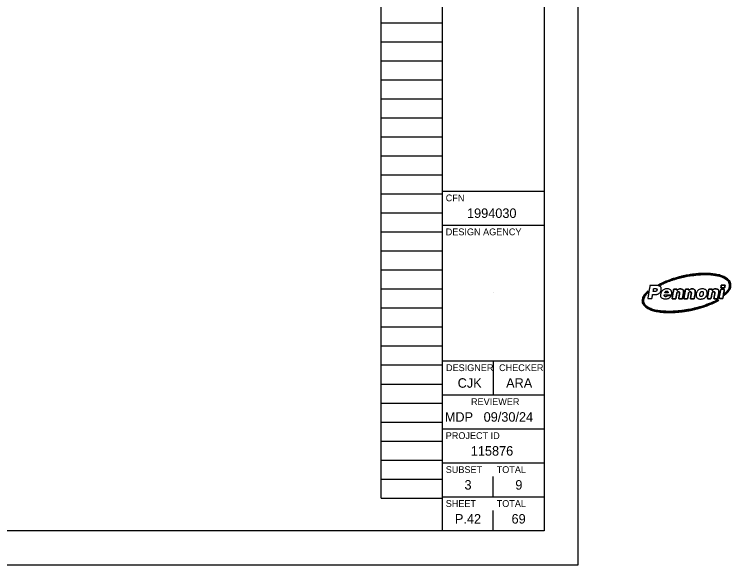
# Model space of a CAD drawing. Extents: x 0 to 36.2, y 0 to 22.
# Drawn here: x 25.7 to 36.25, y 0 to 8.1 of the extents above; entities that cross this region are included whole.
import ezdxf

# ---------------------------------------------------------------- set-up
doc = ezdxf.new("R2010")
doc.units = 0
for name, color, linetype in [('SC_Scratch1', 7, 'Continuous'), ('SH_Border', 7, 'Continuous'), ('SH_Cut_Line', 7, 'Continuous'), ('SH_Data', 7, 'Continuous')]:
    doc.layers.add(name, color=color, linetype=linetype)

msp = doc.modelspace()

# ---------------------------------------------------------------- linework, layer by layer
at = {"layer": 'SC_Scratch1'}
for p, q in [((31.1, 0.98), (31.1, 21.14)), ((32, 0.98), (32, 21.14)), ((31.1, 7.98), (32, 7.98)), ((31.1, 7.7), (32, 7.7)), ((31.1, 7.42), (32, 7.42)), ((31.1, 7.14), (32, 7.14)), ((31.1, 6.86), (32, 6.86)), ((31.1, 6.58), (32, 6.58)), ((31.1, 6.3), (32, 6.3)), ((31.1, 6.02), (32, 6.02)), ((31.1, 5.74), (32, 5.74)), ((31.1, 5.46), (32, 5.46)), ((31.1, 5.18), (32, 5.18)), ((31.1, 4.9), (32, 4.9)), ((31.1, 4.62), (32, 4.62)), ((31.1, 4.34), (32, 4.34)), ((31.1, 4.06), (32, 4.06)), ((31.1, 3.78), (32, 3.78)), ((31.1, 3.5), (32, 3.5)), ((31.1, 3.22), (32, 3.22)), ((31.1, 2.94), (32, 2.94)), ((31.1, 2.66), (32, 2.66)), ((31.1, 2.38), (32, 2.38)), ((31.1, 2.1), (32, 2.1)), ((31.1, 1.82), (32, 1.82)), ((31.1, 1.54), (32, 1.54)), ((31.1, 1.26), (32, 1.26)), ((31.1, 0.98), (32, 0.98))]:
    msp.add_line(p, q, dxfattribs=at)
at = {"layer": 'SH_Border'}
for p, q in [((32, 0.5), (32, 21.5)), ((32, 5.5), (33.5, 5.5)), ((32, 5), (33.5, 5)), ((35.325, 4.003), (35.275, 4.003)), ((32, 3), (33.5, 3)), ((32.75, 3), (32.75, 2.5)), ((32, 2.5), (33.5, 2.5)), ((32, 2), (33.5, 2)), ((32, 1.5), (33.5, 1.5)), ((32, 1), (33.5, 1))]:
    msp.add_line(p, q, dxfattribs=at)
msp.add_lwpolyline([(1.5, 21.5), (33.5, 21.5), (33.5, 0.5), (1.5, 0.5)], close=True, dxfattribs=at)
for points, degree in [([(35.184, 4.121), (35.191, 4.119), (35.197, 4.116), (35.203, 4.115), (35.205, 4.114), (35.208, 4.114), (35.21, 4.115), (35.239, 4.129), (35.267, 4.143), (35.296, 4.155), (35.337, 4.173), (35.38, 4.188), (35.423, 4.201), (35.465, 4.214), (35.507, 4.225), (35.55, 4.234), (35.59, 4.243), (35.63, 4.251), (35.67, 4.256), (35.702, 4.26), (35.734, 4.264), (35.766, 4.267), (35.791, 4.269), (35.817, 4.27), (35.842, 4.271), (35.897, 4.272), (35.952, 4.27), (36.007, 4.262), (36.036, 4.258), (36.066, 4.252), (36.094, 4.242), (36.13, 4.231), (36.163, 4.217), (36.191, 4.191), (36.206, 4.178), (36.218, 4.161), (36.223, 4.141), (36.228, 4.124), (36.23, 4.107), (36.227, 4.089), (36.223, 4.069), (36.213, 4.052), (36.201, 4.036), (36.189, 4.021), (36.175, 4.008), (36.16, 3.995), (36.158, 3.994), (36.157, 3.992), (36.156, 3.99), (36.155, 3.985), (36.154, 3.979), (36.153, 3.973), (36.153, 3.971), (36.152, 3.969), (36.152, 3.965), (36.176, 3.985), (36.199, 4.005), (36.217, 4.029), (36.226, 4.04), (36.234, 4.053), (36.239, 4.066), (36.246, 4.085), (36.246, 4.104), (36.244, 4.123), (36.24, 4.158), (36.224, 4.185), (36.198, 4.208), (36.174, 4.228), (36.147, 4.241), (36.117, 4.252), (36.08, 4.266), (36.042, 4.274), (36.003, 4.279), (35.968, 4.284), (35.933, 4.287), (35.897, 4.288), (35.841, 4.289), (35.785, 4.287), (35.729, 4.281), (35.698, 4.277), (35.667, 4.273), (35.636, 4.268), (35.591, 4.261), (35.546, 4.252), (35.502, 4.24), (35.441, 4.225), (35.382, 4.207), (35.323, 4.184), (35.283, 4.169), (35.243, 4.151), (35.204, 4.131), (35.197, 4.128), (35.191, 4.125), (35.184, 4.121)], 3), ([(35.184, 4.121), (35.191, 4.125), (35.197, 4.128), (35.204, 4.131), (35.243, 4.151), (35.283, 4.169), (35.323, 4.184), (35.382, 4.207), (35.441, 4.225), (35.502, 4.24), (35.546, 4.252), (35.591, 4.261), (35.636, 4.268), (35.667, 4.273), (35.698, 4.277), (35.729, 4.281), (35.785, 4.287), (35.841, 4.289), (35.897, 4.288), (35.933, 4.287), (35.968, 4.284), (36.003, 4.279), (36.042, 4.274), (36.08, 4.266), (36.117, 4.252), (36.147, 4.241), (36.174, 4.228), (36.198, 4.208), (36.224, 4.185), (36.24, 4.158), (36.244, 4.123), (36.246, 4.104), (36.246, 4.085), (36.239, 4.066), (36.234, 4.053), (36.226, 4.04), (36.217, 4.029), (36.199, 4.005), (36.176, 3.985), (36.152, 3.965), (36.152, 3.969), (36.153, 3.971), (36.153, 3.973), (36.154, 3.979), (36.155, 3.985), (36.156, 3.99), (36.157, 3.992), (36.158, 3.994), (36.16, 3.995), (36.175, 4.008), (36.189, 4.021), (36.201, 4.036), (36.213, 4.052), (36.223, 4.069), (36.227, 4.089), (36.23, 4.107), (36.228, 4.124), (36.223, 4.141), (36.218, 4.161), (36.206, 4.178), (36.191, 4.191), (36.163, 4.217), (36.13, 4.231), (36.094, 4.242), (36.066, 4.252), (36.036, 4.258), (36.007, 4.262), (35.952, 4.27), (35.897, 4.272), (35.842, 4.271), (35.817, 4.27), (35.791, 4.269), (35.766, 4.267), (35.734, 4.264), (35.702, 4.26), (35.67, 4.256), (35.63, 4.251), (35.59, 4.243), (35.55, 4.234), (35.507, 4.225), (35.465, 4.214), (35.423, 4.201), (35.38, 4.188), (35.337, 4.173), (35.296, 4.155), (35.267, 4.143), (35.239, 4.129), (35.21, 4.115), (35.208, 4.114), (35.205, 4.114), (35.203, 4.115), (35.197, 4.116), (35.191, 4.119), (35.184, 4.121)], 3), ([(36.164, 4.115), (36.162, 4.103), (36.16, 4.091), (36.157, 4.078), (36.157, 4.077), (36.156, 4.076), (36.155, 4.076), (36.137, 4.076), (36.12, 4.076), (36.102, 4.076), (36.103, 4.086), (36.105, 4.095), (36.107, 4.104), (36.107, 4.106), (36.108, 4.109), (36.108, 4.111), (36.108, 4.115), (36.109, 4.116), (36.113, 4.115), (36.129, 4.115), (36.144, 4.115), (36.16, 4.115), (36.161, 4.115), (36.162, 4.115), (36.164, 4.115)], 3), ([(36.164, 4.115), (36.162, 4.115), (36.161, 4.115), (36.16, 4.115), (36.144, 4.115), (36.129, 4.115), (36.113, 4.115), (36.109, 4.116), (36.108, 4.115), (36.108, 4.111), (36.108, 4.109), (36.107, 4.106), (36.107, 4.104), (36.105, 4.095), (36.103, 4.086), (36.102, 4.076), (36.12, 4.076), (36.137, 4.076), (36.155, 4.076), (36.156, 4.076), (36.157, 4.077), (36.157, 4.078), (36.16, 4.091), (36.162, 4.103), (36.164, 4.115)], 3), ([(36.072, 3.892), (36.072, 3.892), (36.072, 3.893), (36.072, 3.893), (36.062, 3.893), (36.052, 3.893), (36.042, 3.893), (36.04, 3.893), (36.037, 3.892), (36.035, 3.891), (35.997, 3.872), (35.959, 3.855), (35.92, 3.84), (35.862, 3.817), (35.803, 3.798), (35.743, 3.783), (35.7, 3.771), (35.657, 3.762), (35.613, 3.754), (35.588, 3.75), (35.563, 3.746), (35.538, 3.742), (35.513, 3.739), (35.487, 3.736), (35.461, 3.734), (35.437, 3.732), (35.413, 3.73), (35.389, 3.73), (35.361, 3.729), (35.333, 3.728), (35.305, 3.729), (35.274, 3.731), (35.243, 3.733), (35.212, 3.736), (35.174, 3.74), (35.136, 3.748), (35.1, 3.759), (35.068, 3.769), (35.038, 3.782), (35.011, 3.802), (34.995, 3.814), (34.98, 3.829), (34.971, 3.848), (34.959, 3.874), (34.96, 3.9), (34.971, 3.927), (34.98, 3.95), (34.994, 3.97), (35.011, 3.988), (35.016, 3.994), (35.022, 4), (35.022, 4.009), (35.022, 4.014), (35.024, 4.02), (35.025, 4.026), (35.024, 4.025), (35.023, 4.025), (35.022, 4.024), (35.013, 4.014), (35.003, 4.005), (34.994, 3.994), (34.974, 3.972), (34.959, 3.948), (34.95, 3.919), (34.946, 3.902), (34.944, 3.885), (34.947, 3.868), (34.952, 3.841), (34.967, 3.819), (34.986, 3.801), (35.009, 3.78), (35.036, 3.766), (35.064, 3.754), (35.111, 3.735), (35.161, 3.725), (35.211, 3.719), (35.241, 3.716), (35.273, 3.714), (35.304, 3.712), (35.346, 3.711), (35.388, 3.711), (35.43, 3.715), (35.465, 3.717), (35.499, 3.721), (35.533, 3.725), (35.564, 3.729), (35.594, 3.734), (35.625, 3.739), (35.679, 3.749), (35.733, 3.761), (35.786, 3.776), (35.831, 3.789), (35.876, 3.804), (35.92, 3.821), (35.963, 3.838), (36.005, 3.856), (36.046, 3.877), (36.055, 3.882), (36.063, 3.887), (36.072, 3.892)], 3), ([(36.072, 3.892), (36.063, 3.887), (36.055, 3.882), (36.046, 3.877), (36.005, 3.856), (35.963, 3.838), (35.92, 3.821), (35.876, 3.804), (35.831, 3.789), (35.786, 3.776), (35.733, 3.761), (35.679, 3.749), (35.625, 3.739), (35.594, 3.734), (35.564, 3.729), (35.533, 3.725), (35.499, 3.721), (35.465, 3.717), (35.43, 3.715), (35.388, 3.711), (35.346, 3.711), (35.304, 3.712), (35.273, 3.714), (35.241, 3.716), (35.211, 3.719), (35.161, 3.725), (35.111, 3.735), (35.064, 3.754), (35.036, 3.766), (35.009, 3.78), (34.986, 3.801), (34.967, 3.819), (34.952, 3.841), (34.947, 3.868), (34.944, 3.885), (34.946, 3.902), (34.95, 3.919), (34.959, 3.948), (34.974, 3.972), (34.994, 3.994), (35.003, 4.005), (35.013, 4.014), (35.022, 4.024), (35.023, 4.025), (35.024, 4.025), (35.025, 4.026), (35.024, 4.02), (35.022, 4.014), (35.022, 4.009), (35.022, 4), (35.016, 3.994), (35.011, 3.988), (34.994, 3.97), (34.98, 3.95), (34.971, 3.927), (34.96, 3.9), (34.959, 3.874), (34.971, 3.848), (34.98, 3.829), (34.995, 3.814), (35.011, 3.802), (35.038, 3.782), (35.068, 3.769), (35.1, 3.759), (35.136, 3.748), (35.174, 3.74), (35.212, 3.736), (35.243, 3.733), (35.274, 3.731), (35.305, 3.729), (35.333, 3.728), (35.361, 3.729), (35.389, 3.73), (35.413, 3.73), (35.437, 3.732), (35.461, 3.734), (35.487, 3.736), (35.513, 3.739), (35.538, 3.742), (35.563, 3.746), (35.588, 3.75), (35.613, 3.754), (35.657, 3.762), (35.7, 3.771), (35.743, 3.783), (35.803, 3.798), (35.862, 3.817), (35.92, 3.84), (35.959, 3.855), (35.997, 3.872), (36.035, 3.891), (36.037, 3.892), (36.04, 3.893), (36.042, 3.893), (36.052, 3.893), (36.062, 3.893), (36.072, 3.893), (36.072, 3.893), (36.072, 3.892), (36.072, 3.892)], 3), ([(35.196, 4.102), (35.183, 4.108), (35.17, 4.11), (35.156, 4.11), (35.124, 4.111), (35.092, 4.11), (35.061, 4.11), (35.059, 4.11), (35.058, 4.11), (35.057, 4.108), (35.053, 4.086), (35.05, 4.065), (35.046, 4.043), (35.04, 4.009), (35.034, 3.974), (35.028, 3.939), (35.026, 3.932), (35.025, 3.924), (35.024, 3.917)], 3), ([(35.097, 3.977), (35.105, 3.977), (35.112, 3.977), (35.119, 3.977), (35.132, 3.977), (35.145, 3.977), (35.157, 3.98), (35.174, 3.983), (35.189, 3.99), (35.201, 4.002), (35.216, 4.018), (35.222, 4.037), (35.222, 4.059), (35.223, 4.078), (35.214, 4.093), (35.196, 4.102)], 3), ([(35.105, 4.022), (35.108, 4.036), (35.11, 4.05), (35.112, 4.063), (35.113, 4.064), (35.114, 4.065), (35.115, 4.065), (35.126, 4.065), (35.138, 4.067), (35.149, 4.063), (35.159, 4.06), (35.163, 4.054), (35.161, 4.043)], 3), ([(35.161, 4.043), (35.159, 4.031), (35.15, 4.023), (35.137, 4.022), (35.127, 4.022), (35.116, 4.022), (35.105, 4.022)], 3), ([(35.377, 4.008), (35.373, 4.033), (35.36, 4.05), (35.336, 4.057), (35.323, 4.062), (35.309, 4.062), (35.296, 4.061), (35.274, 4.058), (35.255, 4.049), (35.239, 4.032), (35.225, 4.017), (35.217, 4), (35.215, 3.979), (35.212, 3.95), (35.224, 3.926), (35.253, 3.917), (35.269, 3.912), (35.286, 3.911), (35.302, 3.914), (35.32, 3.916), (35.336, 3.922), (35.35, 3.934), (35.358, 3.941), (35.364, 3.949), (35.368, 3.959)], 3), ([(35.275, 4.003), (35.276, 4.015), (35.286, 4.025), (35.298, 4.027), (35.304, 4.028), (35.31, 4.028), (35.315, 4.025), (35.323, 4.021), (35.327, 4.013), (35.325, 4.003)], 3), ([(35.383, 3.916), (35.383, 3.915), (35.384, 3.915), (35.385, 3.915), (35.402, 3.915), (35.419, 3.915), (35.436, 3.915), (35.438, 3.915), (35.438, 3.916), (35.439, 3.918), (35.44, 3.926), (35.441, 3.935), (35.443, 3.943), (35.446, 3.96), (35.449, 3.978), (35.453, 3.995), (35.455, 4.005), (35.459, 4.013), (35.469, 4.015), (35.482, 4.019), (35.496, 4.016), (35.494, 3.997), (35.492, 3.982), (35.489, 3.968), (35.487, 3.954), (35.485, 3.941), (35.482, 3.928), (35.48, 3.916), (35.481, 3.915), (35.481, 3.915), (35.482, 3.915), (35.499, 3.915), (35.516, 3.915), (35.533, 3.915), (35.535, 3.915), (35.536, 3.916), (35.536, 3.919), (35.54, 3.942), (35.545, 3.966), (35.549, 3.99), (35.551, 4.002), (35.553, 4.015), (35.551, 4.027), (35.549, 4.043), (35.54, 4.054), (35.524, 4.058), (35.503, 4.064), (35.483, 4.06), (35.466, 4.045), (35.462, 4.042), (35.458, 4.038), (35.454, 4.035), (35.456, 4.042), (35.457, 4.049), (35.458, 4.057), (35.442, 4.057), (35.425, 4.057), (35.409, 4.056), (35.408, 4.056), (35.407, 4.055), (35.407, 4.054), (35.406, 4.05), (35.405, 4.045), (35.405, 4.041), (35.399, 4.011), (35.394, 3.98), (35.389, 3.95), (35.387, 3.938), (35.385, 3.927), (35.383, 3.916)], 3), ([(35.383, 3.916), (35.385, 3.927), (35.387, 3.938), (35.389, 3.95), (35.394, 3.98), (35.399, 4.011), (35.405, 4.041), (35.405, 4.045), (35.406, 4.05), (35.407, 4.054), (35.407, 4.055), (35.408, 4.056), (35.409, 4.056), (35.425, 4.057), (35.442, 4.057), (35.458, 4.057), (35.457, 4.049), (35.456, 4.042), (35.454, 4.035), (35.458, 4.038), (35.462, 4.042), (35.466, 4.045), (35.483, 4.06), (35.503, 4.064), (35.524, 4.058), (35.54, 4.054), (35.549, 4.043), (35.551, 4.027), (35.553, 4.015), (35.551, 4.002), (35.549, 3.99), (35.545, 3.966), (35.54, 3.942), (35.536, 3.919), (35.536, 3.916), (35.535, 3.915), (35.533, 3.915), (35.516, 3.915), (35.499, 3.915), (35.482, 3.915), (35.481, 3.915), (35.481, 3.915), (35.48, 3.916), (35.482, 3.928), (35.485, 3.941), (35.487, 3.954), (35.489, 3.968), (35.492, 3.982), (35.494, 3.997), (35.496, 4.016), (35.482, 4.019), (35.469, 4.015), (35.459, 4.013), (35.455, 4.005), (35.453, 3.995), (35.449, 3.978), (35.446, 3.96), (35.443, 3.943), (35.441, 3.935), (35.44, 3.926), (35.439, 3.918), (35.438, 3.916), (35.438, 3.915), (35.436, 3.915), (35.419, 3.915), (35.402, 3.915), (35.385, 3.915), (35.384, 3.915), (35.383, 3.915), (35.383, 3.916)], 3), ([(35.556, 3.916), (35.556, 3.915), (35.556, 3.915), (35.557, 3.915), (35.574, 3.915), (35.591, 3.915), (35.609, 3.915), (35.61, 3.915), (35.611, 3.917), (35.612, 3.918), (35.615, 3.935), (35.618, 3.952), (35.621, 3.969), (35.623, 3.979), (35.624, 3.99), (35.627, 4), (35.631, 4.013), (35.643, 4.019), (35.656, 4.016), (35.662, 4.015), (35.665, 4.011), (35.666, 4.005), (35.667, 4.002), (35.667, 3.999), (35.667, 3.996), (35.665, 3.985), (35.663, 3.973), (35.661, 3.962), (35.659, 3.947), (35.656, 3.931), (35.653, 3.916), (35.654, 3.915), (35.654, 3.915), (35.654, 3.915), (35.671, 3.915), (35.689, 3.915), (35.706, 3.915), (35.707, 3.915), (35.709, 3.917), (35.709, 3.918), (35.713, 3.941), (35.717, 3.963), (35.721, 3.985), (35.723, 3.997), (35.725, 4.009), (35.725, 4.022), (35.725, 4.037), (35.719, 4.05), (35.703, 4.056), (35.683, 4.064), (35.663, 4.062), (35.645, 4.05), (35.639, 4.045), (35.633, 4.04), (35.627, 4.035), (35.629, 4.043), (35.63, 4.049), (35.631, 4.057), (35.615, 4.057), (35.599, 4.057), (35.583, 4.057), (35.58, 4.057), (35.58, 4.055), (35.58, 4.053), (35.576, 4.029), (35.571, 4.005), (35.567, 3.981), (35.563, 3.96), (35.56, 3.938), (35.556, 3.916)], 3), ([(35.556, 3.916), (35.56, 3.938), (35.563, 3.96), (35.567, 3.981), (35.571, 4.005), (35.576, 4.029), (35.58, 4.053), (35.58, 4.055), (35.58, 4.057), (35.583, 4.057), (35.599, 4.057), (35.615, 4.057), (35.631, 4.057), (35.63, 4.049), (35.629, 4.043), (35.627, 4.035), (35.633, 4.04), (35.639, 4.045), (35.645, 4.05), (35.663, 4.062), (35.683, 4.064), (35.703, 4.056), (35.719, 4.05), (35.725, 4.037), (35.725, 4.022), (35.725, 4.009), (35.723, 3.997), (35.721, 3.985), (35.717, 3.963), (35.713, 3.941), (35.709, 3.918), (35.709, 3.917), (35.707, 3.915), (35.706, 3.915), (35.689, 3.915), (35.671, 3.915), (35.654, 3.915), (35.654, 3.915), (35.654, 3.915), (35.653, 3.916), (35.656, 3.931), (35.659, 3.947), (35.661, 3.962), (35.663, 3.973), (35.665, 3.985), (35.667, 3.996), (35.667, 3.999), (35.667, 4.002), (35.666, 4.005), (35.665, 4.011), (35.662, 4.015), (35.656, 4.016), (35.643, 4.019), (35.631, 4.013), (35.627, 4), (35.624, 3.99), (35.623, 3.979), (35.621, 3.969), (35.618, 3.952), (35.615, 3.935), (35.612, 3.918), (35.611, 3.917), (35.61, 3.915), (35.609, 3.915), (35.591, 3.915), (35.574, 3.915), (35.557, 3.915), (35.556, 3.915), (35.556, 3.915), (35.556, 3.916)], 3), ([(35.899, 4.008), (35.897, 4.03), (35.886, 4.045), (35.866, 4.054), (35.847, 4.062), (35.827, 4.062), (35.807, 4.058), (35.783, 4.053), (35.764, 4.041), (35.75, 4.02), (35.749, 4.018), (35.748, 4.015), (35.747, 4.013), (35.746, 4.011), (35.745, 4.009), (35.744, 4.007), (35.739, 3.996), (35.736, 3.984), (35.736, 3.972), (35.736, 3.97), (35.736, 3.967), (35.736, 3.965), (35.736, 3.957), (35.738, 3.95), (35.741, 3.944), (35.741, 3.943), (35.742, 3.941), (35.742, 3.94), (35.743, 3.939), (35.744, 3.938), (35.744, 3.937), (35.747, 3.934), (35.749, 3.93), (35.753, 3.927), (35.755, 3.926), (35.757, 3.924), (35.759, 3.923), (35.759, 3.922), (35.76, 3.922), (35.761, 3.922), (35.762, 3.921), (35.763, 3.92), (35.764, 3.92), (35.766, 3.919), (35.768, 3.918), (35.77, 3.917), (35.781, 3.912), (35.793, 3.911), (35.805, 3.91)], 3), ([(35.792, 3.971), (35.793, 3.987), (35.795, 4.001), (35.804, 4.013), (35.809, 4.019), (35.816, 4.023), (35.824, 4.023), (35.833, 4.023), (35.839, 4.02), (35.841, 4.011), (35.842, 4.005), (35.843, 3.998), (35.843, 3.991)], 3), ([(35.926, 4.056), (35.918, 4.009), (35.91, 3.962), (35.902, 3.915), (35.921, 3.915), (35.939, 3.915), (35.957, 3.915), (35.96, 3.93), (35.962, 3.944), (35.965, 3.958), (35.967, 3.971), (35.969, 3.984), (35.972, 3.996), (35.975, 4.01), (35.985, 4.017), (35.998, 4.017), (36.007, 4.016), (36.012, 4.011), (36.013, 4.003), (36.013, 4), (36.013, 3.997), (36.013, 3.994), (36.01, 3.975), (36.006, 3.956), (36.003, 3.937), (36.002, 3.93), (36, 3.923), (35.999, 3.915), (36.018, 3.915), (36.036, 3.915), (36.055, 3.915), (36.055, 3.917), (36.055, 3.918), (36.055, 3.919), (36.059, 3.94), (36.063, 3.962), (36.067, 3.983), (36.069, 3.997), (36.072, 4.01), (36.071, 4.025), (36.07, 4.041), (36.061, 4.053), (36.045, 4.058), (36.02, 4.065), (35.999, 4.059), (35.98, 4.041), (35.978, 4.039), (35.976, 4.037), (35.974, 4.035), (35.974, 4.035), (35.974, 4.035), (35.974, 4.036), (35.975, 4.042), (35.976, 4.049), (35.977, 4.056), (35.96, 4.056), (35.943, 4.056), (35.926, 4.056)], 3), ([(35.926, 4.056), (35.943, 4.056), (35.96, 4.056), (35.977, 4.056), (35.976, 4.049), (35.975, 4.042), (35.974, 4.036), (35.974, 4.035), (35.974, 4.035), (35.974, 4.035), (35.976, 4.037), (35.978, 4.039), (35.98, 4.041), (35.999, 4.059), (36.02, 4.065), (36.045, 4.058), (36.061, 4.053), (36.07, 4.041), (36.071, 4.025), (36.072, 4.01), (36.069, 3.997), (36.067, 3.983), (36.063, 3.962), (36.059, 3.94), (36.055, 3.919), (36.055, 3.918), (36.055, 3.917), (36.055, 3.915), (36.036, 3.915), (36.018, 3.915), (35.999, 3.915), (36, 3.923), (36.002, 3.93), (36.003, 3.937), (36.006, 3.956), (36.01, 3.975), (36.013, 3.994), (36.013, 3.997), (36.013, 4), (36.013, 4.003), (36.012, 4.011), (36.007, 4.016), (35.998, 4.017), (35.985, 4.017), (35.975, 4.01), (35.972, 3.996), (35.969, 3.984), (35.967, 3.971), (35.965, 3.958), (35.962, 3.944), (35.96, 3.93), (35.957, 3.915), (35.939, 3.915), (35.921, 3.915), (35.902, 3.915), (35.91, 3.962), (35.918, 4.009), (35.926, 4.056)], 3), ([(36.129, 3.917), (36.111, 3.917), (36.093, 3.917), (36.074, 3.917), (36.082, 3.964), (36.09, 4.01), (36.098, 4.057), (36.117, 4.057), (36.135, 4.057), (36.154, 4.057), (36.146, 4.01), (36.137, 3.964), (36.129, 3.917)], 3), ([(36.129, 3.917), (36.137, 3.964), (36.146, 4.01), (36.154, 4.057), (36.135, 4.057), (36.117, 4.057), (36.098, 4.057), (36.09, 4.01), (36.082, 3.964), (36.074, 3.917), (36.093, 3.917), (36.111, 3.917), (36.129, 3.917)], 3), ([(35.024, 3.917), (35.025, 3.917), (35.025, 3.917), (35.026, 3.917), (35.045, 3.917), (35.065, 3.917), (35.084, 3.917), (35.087, 3.917), (35.087, 3.918), (35.087, 3.92), (35.089, 3.931), (35.091, 3.942), (35.093, 3.954), (35.095, 3.961), (35.096, 3.969), (35.097, 3.977)], 3), ([(35.368, 3.959), (35.351, 3.959), (35.334, 3.959), (35.317, 3.958), (35.316, 3.958), (35.315, 3.957), (35.314, 3.957), (35.31, 3.954), (35.306, 3.95), (35.302, 3.948), (35.285, 3.942), (35.268, 3.951), (35.269, 3.97), (35.269, 3.974), (35.27, 3.975), (35.274, 3.975), (35.306, 3.975), (35.338, 3.975), (35.371, 3.975), (35.372, 3.975), (35.374, 3.975), (35.376, 3.975)], 3), ([(35.376, 3.975), (35.378, 3.986), (35.379, 3.997), (35.377, 4.008)], 2), ([(35.843, 3.991), (35.842, 3.981), (35.839, 3.971), (35.834, 3.962), (35.828, 3.952), (35.818, 3.947), (35.808, 3.949), (35.801, 3.95), (35.796, 3.953), (35.794, 3.959), (35.793, 3.964), (35.792, 3.969), (35.792, 3.971)], 3), ([(35.805, 3.91), (35.812, 3.911), (35.819, 3.912), (35.826, 3.913), (35.845, 3.916), (35.862, 3.925), (35.875, 3.939), (35.893, 3.959), (35.9, 3.982), (35.899, 4.008)], 3)]:
    msp.add_open_spline(points, degree=degree, dxfattribs=at)
at = {"layer": 'SH_Cut_Line'}
msp.add_lwpolyline([(0, 0), (34, 0), (34, 22), (0, 22)], close=True, dxfattribs=at)
at = {"layer": 'SH_Data'}
for p, q in [((32.75, 4), (32.75, 4)), ((32.75, 1), (32.75, 1.3)), ((32.75, 0.5), (32.75, 0.8)), ((32.375, 0.675), (32.375, 0.675))]:
    msp.add_line(p, q, dxfattribs=at)

# ---------------------------------------------------------------- texts
for s, height, p in [('CFN', 0.1, (32.05, 5.35)), ('1994030', 0.14, (32.363, 5.105)), ('DESIGN AGENCY', 0.1, (32.05, 4.85)), ('DESIGNER', 0.1, (32.054, 2.85)), ('CHECKER', 0.1, (32.835, 2.85)), ('CJK', 0.14, (32.226, 2.605)), ('ARA', 0.14, (32.939, 2.605)), ('REVIEWER', 0.1, (32.422, 2.35)), ('MDP', 0.14, (32.036, 2.105)), ('09/30/24', 0.14, (32.608, 2.105)), ('PROJECT ID', 0.1, (32.05, 1.85)), ('115876', 0.14, (32.419, 1.605)), ('SUBSET', 0.1, (32.05, 1.35)), ('TOTAL', 0.1, (32.8, 1.35)), ('3', 0.14, (32.326, 1.105)), ('9', 0.14, (33.075, 1.105)), ('SHEET', 0.1, (32.05, 0.85)), ('TOTAL', 0.1, (32.8, 0.85)), ('P.42', 0.14, (32.185, 0.605)), ('69', 0.14, (33.019, 0.605))]:
    msp.add_text(s, height=height, dxfattribs=at).set_placement(p)

doc.saveas('drawing.dxf')
